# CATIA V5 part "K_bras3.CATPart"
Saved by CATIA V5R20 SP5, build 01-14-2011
Part number: bras3
Publications: "Point_centre_liaison_pivot23", "Plan_référence", "Plan.5", "Point.3", "Plan.10", "Plan.11", "Droite.1", "Plan.8", "Plan.18", "Plan.9", "Plan.12", "point_centre_liaison_glissière", "Droite.2", "Plan.14", "Plan.17"
Bounding box of the stored display mesh (mm): x -96.226 to -27.726, y -508 to -448, z -44.99 to 101.305
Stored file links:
  G:\Khaled_CFAO_2011\SIL\SIL_GR2\pfradet\pfradet\Khaled\CAD_ThinkMOTION\K_bras3.CATPart
  U:\TNHIKMOTION\ass_cutting_device.CATProduct
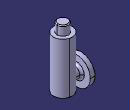
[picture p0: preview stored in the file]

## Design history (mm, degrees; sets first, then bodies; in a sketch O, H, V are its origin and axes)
External parameters (linked from other documents)
  External.Longueur_bras3 = 110 mm
Point1 "Point_centre_liaison_pivot23": linked copy from another document
Sketch1 on Plane4, origin (-22.8569, -372.0878, 81.3048), H (-0.2487, -0.9686, 0), V (0.9686, -0.2487, 0)
  circle A1 centre (100, 0) radius 20
  point P1 (100, 0)
  coincidence: P1 H
Pad1: profile Sketch1, direction (0, 0, -1), length 110 {= External.Longueur_bras3}
Point2: linked copy from another document
Sketch2 on Plane4, origin (0, 0, 81.3048), H (1, 0, 0), V (0, 1, 0)
  circle A1 centre (-47.7259, -468.9461) radius 12
  point P1 (-47.7259, -468.9461)
  reference projected point E1 (-47.7259, -468.9461) from Point2
  coincidence: P1 E1
Pad2: profile Sketch2, direction (0, 0, 1), length 20
Line1: type Normal, RefPoint Point3, RefSkin Plane1, Start 0, End 20
Line2: linked copy from another document
Point3 "point_centre_liaison_glissière": linked copy from another document
Plane1: type Offset, RefPlane Plane6, Offset 0
Set1
  Plane2: stored without definition
Set2
  Plane3 "Plan_référence": linked copy from another document
  Plane4 to Plane8: linked copy from another document
Set3
  Plane9: type Offset, RefPlane end face of Pad1, Offset 0, reversed
  Plane10: type Offset, RefPlane Plane7, Offset 0
  Plane11: type OffsetPt, RefPlane Plane9, RefPoint vertex of Line2
Body1 (main body)
  Chamfer1: length 2, angle 45, on end face of Pad2
  Sketch3 on Plane9, origin (0, 0, -28.6952), H (1, 0, 0), V (0, 1, 0)
    line L1 (-46.2259, -479.4461) -> (-49.2259, -479.4461)
    line L2 (-49.2259, -479.4461) -> (-49.2259, -458.4461)
    line L3 (-49.2259, -458.4461) -> (-46.2259, -458.4461)
    line L4 (-46.2259, -458.4461) -> (-46.2259, -479.4461)
    reference projected point E1 (-47.7259, -468.9461) from Point1
    reference projected point E2 (-47.7259, -468.9461) from Point1
    length L4 = 21
    length L3 = 3
    distance E1 L4 = 1.5
    distance E2 L3 = 10.5
    horizontal: L1 H, L3 H
    vertical: L2 V, L4 V
  Pocket1: profile Sketch3, direction (0, 0, 1), length 20
  Sketch4 on face of Pocket1 from Sketch3.L4, origin (-46.2259, 0, 0), H (0, -1, 0), V (0, 0, 1)
    circle A1 centre (478, -15) radius 12
  Pad3: profile Sketch4, direction (-1, 0, 0), length 40
  Sketch5 on end face of Pad3, origin (-86.2259, 0, 0), H (0, -1, 0), V (0, 0, 1)
    circle A1 centre (478, -15) radius 30
  Pad4: profile Sketch5, direction (-1, 0, 0), length 10
  Fillet1: radius 5, on edge [face of Pad3 from Sketch4.A1 | face of Pad1 from Sketch1.A1]
  Fillet2: radius 5, on edge [face of Pad3 from Sketch4.A1 | start face of Pad4]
